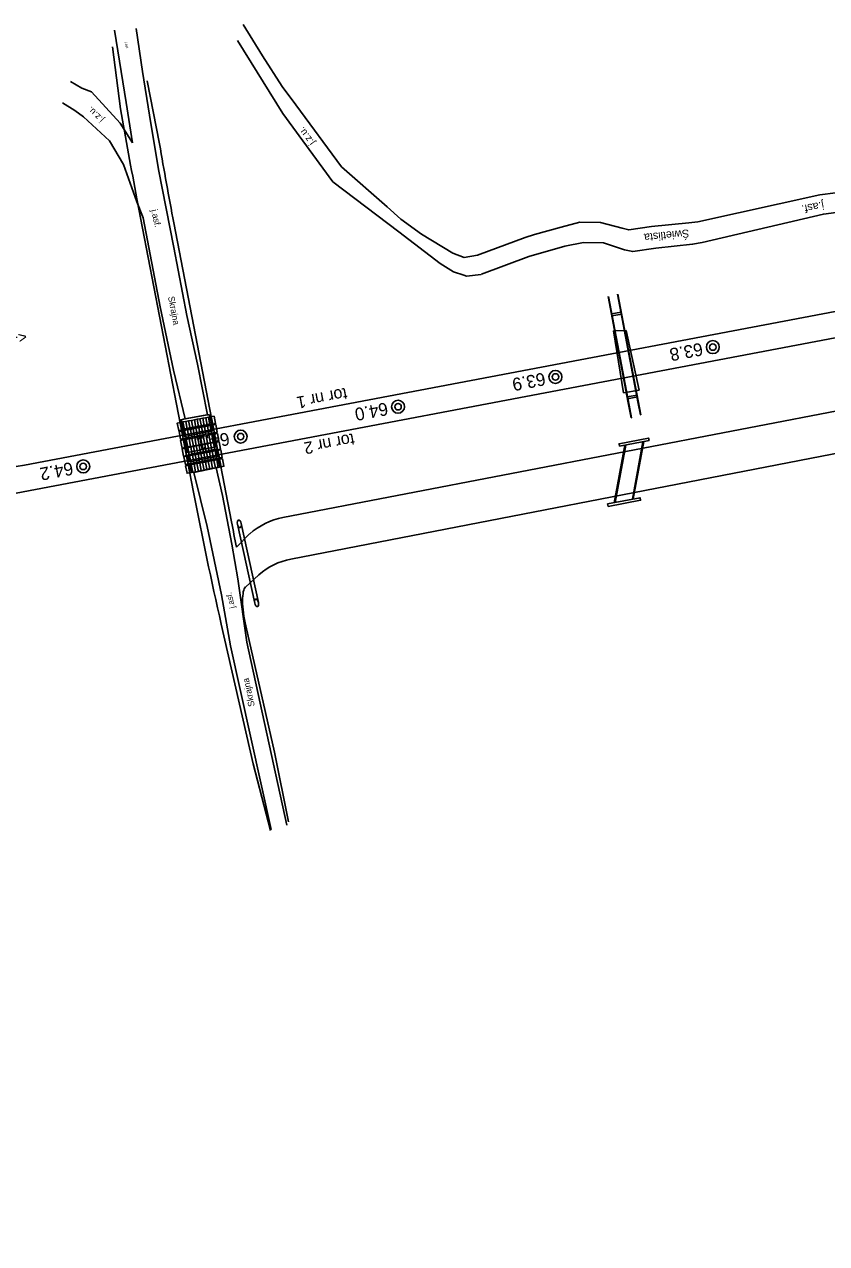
# Model space of a CAD drawing. Extents: x 6541740 to 6556805, y 5525233 to 5530361.
# Drawn here: x 6556529 to 6556654.1, y 5525917.2 to 5526107.6 of the extents above; entities that cross this region are included whole.
import ezdxf

# ---------------------------------------------------------------- set-up
doc = ezdxf.new("R2010")
doc.units = 0
for name, color, linetype in [('Default', 7, 'Continuous'), ('TOR_PS_OPIS_T-numeracja torow i rozjazdow', 7, 'Continuous'), ('TOR_SCH-hektometry', 7, 'Continuous'), ('TOR_SCH-obiekty istniejace', 7, 'Continuous'), ('TOR_SCH-obiekty projektowane', 7, 'Continuous'), ('TOR_SCH-opisy dodatkowe', 7, 'Continuous'), ('TOR_SCH-przejazdy+drogi istniejace', 7, 'Continuous'), ('TOR_SCH-przejazdy+drogi projektowane', 7, 'Continuous'), ('TOR_SCH-tory projektowane', 7, 'Continuous')]:
    doc.layers.add(name, color=color, linetype=linetype)

# ---------------------------------------------------------------- blocks, each defined once
blk = doc.blocks.new('4010_1')
at = {"layer": 'Default'}
for radius in [0.75, 0.375]:
    blk.add_circle((0, 0), radius, dxfattribs=at)

msp = doc.modelspace()

# ---------------------------------------------------------------- linework, layer by layer
at = {"layer": 'Default'}
for points in [[(6556556.79, 5526046.09), (6556557.02, 5526044.91), (6556556.58, 5526044.83), (6556556.35, 5526046.01)], [(6556557.5, 5526044.85), (6556557.72, 5526043.67), (6556557.28, 5526043.59), (6556557.06, 5526044.77)], [(6556557.94, 5526044.94), (6556558.17, 5526043.76), (6556557.72, 5526043.67), (6556557.5, 5526044.85)], [(6556556.23, 5526041.84), (6556556.45, 5526040.67), (6556556.01, 5526040.58), (6556555.78, 5526041.76)]]:
    msp.add_lwpolyline(points, close=True, dxfattribs=at)
at = {"layer": 'TOR_SCH-obiekty istniejace'}
for p, q in [((6556620.88, 5526059.73), (6556622.87, 5526059.79)), ((6556622.44, 5526050.06), (6556620.88, 5526059.73)), ((6556622.87, 5526059.79), (6556624.87, 5526050.5)), ((6556624.87, 5526050.5), (6556622.44, 5526050.06))]:
    msp.add_line(p, q, dxfattribs=at)
at = {"layer": 'TOR_SCH-obiekty projektowane'}
for p, q in [((6556620.04, 5526065.09), (6556623.18, 5526048.52)), ((6556620.11, 5526065.11), (6556623.33, 5526048.14)), ((6556621.5, 5526065.45), (6556624.73, 5526048.4)), ((6556621.57, 5526065.46), (6556624.73, 5526048.81)), ((6556623.18, 5526048.52), (6556623.63, 5526046.17)), ((6556623.33, 5526048.14), (6556623.7, 5526046.18)), ((6556624.73, 5526048.81), (6556625.15, 5526046.61)), ((6556624.73, 5526048.4), (6556625.07, 5526046.6)), ((6556622.65, 5526041.89), (6556621, 5526032.91)), ((6556622.78, 5526041.91), (6556621.14, 5526032.94)), ((6556625.48, 5526042.43), (6556623.84, 5526033.46)), ((6556625.62, 5526042.46), (6556623.97, 5526033.49)), ((6556562.2, 5526029.53), (6556564.89, 5526017.21)), ((6556562.78, 5526029.67), (6556565.47, 5526017.35))]:
    msp.add_line(p, q, dxfattribs=at)
for points in [[(6556620.56, 5526062.37), (6556622.1, 5526062.66)], [(6556620.61, 5526062.07), (6556622.16, 5526062.36)], [(6556623.01, 5526049.41), (6556624.56, 5526049.71)], [(6556623.07, 5526049.12), (6556624.61, 5526049.41)], [(6556623.63, 5526046.17), (6556623.7, 5526046.18)], [(6556625.07, 5526046.6), (6556625.15, 5526046.61)]]:
    msp.add_lwpolyline(points, dxfattribs=at)
for points in [[(6556621.83, 5526041.73), (6556621.76, 5526042.12), (6556626.36, 5526043), (6556626.43, 5526042.61)], [(6556620.03, 5526032.31), (6556619.95, 5526032.71), (6556625.02, 5526033.68), (6556625.1, 5526033.29)]]:
    msp.add_lwpolyline(points, close=True, dxfattribs=at)
for centre in [(6556562.49, 5526029.6), (6556565.18, 5526017.28)]:
    msp.add_ellipse(centre, major_axis=(-0.124, 0.587), ratio=0.500167, dxfattribs=at)
at = {"layer": 'TOR_SCH-przejazdy+drogi istniejace'}
for p, q in [((6556566.12, 5526102.68), (6556563.09, 5526107.58)), ((6556562.19, 5526105.07), (6556569.27, 5526093.69)), ((6556569.19, 5526097.91), (6556566.12, 5526102.68)), ((6556543.91, 5526092.16), (6556539.4, 5526097.06)), ((6556571.32, 5526095), (6556569.19, 5526097.91)), ((6556545.84, 5526089.07), (6556544.84, 5526095.37)), ((6556578.46, 5526085.36), (6556571.32, 5526095)), ((6556538.15, 5526093.17), (6556542.21, 5526089.4)), ((6556548.46, 5526093.42), (6556549.89, 5526084.94)), ((6556569.27, 5526093.69), (6556577.09, 5526082.98)), ((6556545.84, 5526089.07), (6556543.91, 5526092.16)), ((6556542.21, 5526089.4), (6556544.42, 5526085.72)), ((6556544.42, 5526085.72), (6556546.5, 5526079.87)), ((6556585.58, 5526079.09), (6556578.46, 5526085.36)), ((6556577.09, 5526082.98), (6556587.37, 5526075.17)), ((6556587.69, 5526077.17), (6556585.58, 5526079.09)), ((6556590.92, 5526074.81), (6556587.69, 5526077.17)), ((6556587.37, 5526075.17), (6556593.84, 5526070.23)), ((6556595.79, 5526071.85), (6556590.92, 5526074.81)), ((6556593.84, 5526070.23), (6556595.9, 5526068.96)), ((6556556.62, 5526037.87), (6556557.78, 5526038.17)), ((6556567.45, 5525981.86), (6556561.11, 5526010.54)), ((6556563.65, 5526011.12), (6556569.88, 5525982.58))]:
    msp.add_line(p, q, dxfattribs=at)
for points in [[(6556544.84, 5526095.37), (6556543.03, 5526106.68)], [(6556546.4, 5526106.96), (6556547.4, 5526100.21), (6556548.46, 5526093.42)], [(6556539.4, 5526097.06), (6556537.92, 5526097.65), (6556536.16, 5526098.68)], [(6556538.15, 5526093.17), (6556536.82, 5526094.13), (6556534.92, 5526095.32)], [(6556547.48, 5526077.39), (6556550.14, 5526063.49), (6556552.22, 5526053.59), (6556554.05, 5526045.99), (6556557.51, 5526046.62), (6556555.96, 5526054.51), (6556554.32, 5526062.14), (6556552.27, 5526072.74), (6556549.89, 5526084.94)], [(6556634.04, 5526076.74), (6556653.08, 5526080.96), (6556662.87, 5526082.23), (6556670.25, 5526085.15), (6556671.73, 5526085.15), (6556673.8, 5526083.86)], [(6556634.74, 5526073.51), (6556653.64, 5526077.98), (6556663.43, 5526079.25), (6556670.97, 5526081.74), (6556670.97, 5526081.74), (6556673.35, 5526080.43)], [(6556546.5, 5526079.87), (6556547.48, 5526077.39)], [(6556599.66, 5526071.57), (6556607.07, 5526074.33), (6556608.55, 5526074.76), (6556612.72, 5526075.95), (6556615.61, 5526076.71), (6556618.84, 5526076.67), (6556622.22, 5526075.78), (6556623.25, 5526075.5), (6556626.83, 5526076.01), (6556632.64, 5526076.59), (6556634.04, 5526076.74)], [(6556600.26, 5526068.57), (6556607.67, 5526071.33), (6556613.31, 5526072.95), (6556616.18, 5526073.53), (6556619.34, 5526073.49), (6556622.58, 5526072.37), (6556623.88, 5526072.12), (6556627.46, 5526072.63), (6556633.22, 5526073.25), (6556634.74, 5526073.51)], [(6556595.79, 5526071.85), (6556597.57, 5526071.19), (6556599.66, 5526071.57)], [(6556595.9, 5526068.96), (6556597.55, 5526068.42), (6556597.94, 5526068.3), (6556600.24, 5526068.56)], [(6556563.65, 5526011.12), (6556562.26, 5526021.02), (6556561.34, 5526026.41), (6556559.86, 5526034.01), (6556558.88, 5526038.37), (6556555.37, 5526037.64), (6556557.46, 5526029.19), (6556559.71, 5526018.51), (6556561.11, 5526010.54)]]:
    msp.add_lwpolyline(points, dxfattribs=at)
for points in [[(6556557.84, 5526046.63), (6556558.13, 5526045.2), (6556553.7, 5526044.39), (6556553.4, 5526045.87), (6556553.99, 5526045.98), (6556557.44, 5526046.61)], [(6556553.7, 5526044.39), (6556558.14, 5526045.2), (6556558.35, 5526044.13), (6556553.92, 5526043.26)], [(6556553.96, 5526042.94), (6556558.38, 5526043.83), (6556558.83, 5526041.61), (6556554.39, 5526040.75)], [(6556554.44, 5526040.39), (6556558.87, 5526041.27), (6556559.11, 5526040.11), (6556554.66, 5526039.27)], [(6556554.75, 5526038.89), (6556559.19, 5526039.74), (6556559.44, 5526038.49), (6556558.95, 5526038.39), (6556555.44, 5526037.65), (6556555.01, 5526037.61)]]:
    msp.add_lwpolyline(points, close=True, dxfattribs=at)
at = {"layer": 'TOR_SCH-przejazdy+drogi projektowane'}
for p, q in [((6556543.97, 5526094.39), (6556542.71, 5526104.08)), ((6556548.11, 5526098.78), (6556550.05, 5526088.91)), ((6556555.34, 5526034.54), (6556546.52, 5526080.37)), ((6556552.28, 5526076.59), (6556561.27, 5526029.93)), ((6556679.79, 5526051.86), (6556569.29, 5526030.59)), ((6556570.53, 5526024.1), (6556677.39, 5526044.81)), ((6556564.1, 5526028.03), (6556562.05, 5526025.96)), ((6556563.45, 5526019.74), (6556565.55, 5526021.66))]:
    msp.add_line(p, q, dxfattribs=at)
for points in [[(6556553.7, 5526045.51), (6556553.92, 5526044.33), (6556553.48, 5526044.25), (6556553.26, 5526045.42)], [(6556554.14, 5526045.59), (6556554.37, 5526044.41), (6556553.92, 5526044.33), (6556553.7, 5526045.51)], [(6556554.58, 5526045.68), (6556554.81, 5526044.5), (6556554.37, 5526044.41), (6556554.14, 5526045.59)], [(6556555.03, 5526045.76), (6556555.25, 5526044.58), (6556554.81, 5526044.5), (6556554.58, 5526045.68)], [(6556555.47, 5526045.84), (6556555.69, 5526044.66), (6556555.25, 5526044.58), (6556555.03, 5526045.76)], [(6556555.91, 5526045.93), (6556556.14, 5526044.75), (6556555.69, 5526044.66), (6556555.47, 5526045.84)], [(6556556.35, 5526046.01), (6556556.58, 5526044.83), (6556556.14, 5526044.75), (6556555.91, 5526045.93)], [(6556557.24, 5526046.18), (6556557.46, 5526045), (6556557.02, 5526044.91), (6556556.79, 5526046.09)], [(6556557.68, 5526046.26), (6556557.9, 5526045.08), (6556557.46, 5526045), (6556557.24, 5526046.18)], [(6556558.12, 5526046.34), (6556558.35, 5526045.17), (6556557.9, 5526045.08), (6556557.68, 5526046.26)], [(6556558.56, 5526046.43), (6556558.79, 5526045.25), (6556558.35, 5526045.17), (6556558.12, 5526046.34)], [(6556553.26, 5526045.42), (6556553.48, 5526044.25), (6556553.04, 5526044.16), (6556552.81, 5526045.34)], [(6556553.52, 5526044.1), (6556553.74, 5526042.92), (6556553.3, 5526042.84), (6556553.08, 5526044.02)], [(6556553.96, 5526044.18), (6556554.19, 5526043.01), (6556553.74, 5526042.92), (6556553.52, 5526044.1)], [(6556554.4, 5526044.27), (6556554.63, 5526043.09), (6556554.19, 5526043.01), (6556553.96, 5526044.18)], [(6556554.85, 5526044.35), (6556555.07, 5526043.17), (6556554.63, 5526043.09), (6556554.4, 5526044.27)], [(6556555.29, 5526044.44), (6556555.51, 5526043.26), (6556555.07, 5526043.17), (6556554.85, 5526044.35)], [(6556555.73, 5526044.52), (6556555.96, 5526043.34), (6556555.51, 5526043.26), (6556555.29, 5526044.44)], [(6556556.17, 5526044.6), (6556556.4, 5526043.42), (6556555.96, 5526043.34), (6556555.73, 5526044.52)], [(6556556.61, 5526044.69), (6556556.84, 5526043.51), (6556556.4, 5526043.42), (6556556.17, 5526044.6)], [(6556557.06, 5526044.77), (6556557.28, 5526043.59), (6556556.84, 5526043.51), (6556556.61, 5526044.69)], [(6556558.38, 5526045.02), (6556558.61, 5526043.84), (6556558.17, 5526043.76), (6556557.94, 5526044.94)], [(6556558.64, 5526043.62), (6556558.86, 5526042.44), (6556558.42, 5526042.36), (6556558.2, 5526043.54)], [(6556558.83, 5526045.1), (6556559.05, 5526043.93), (6556558.61, 5526043.84), (6556558.38, 5526045.02)], [(6556559.08, 5526043.7), (6556559.3, 5526042.52), (6556558.86, 5526042.44), (6556558.64, 5526043.62)], [(6556553.77, 5526042.7), (6556554, 5526041.52), (6556553.56, 5526041.44), (6556553.33, 5526042.62)], [(6556554.22, 5526042.78), (6556554.44, 5526041.61), (6556554, 5526041.52), (6556553.77, 5526042.7)], [(6556554.66, 5526042.87), (6556554.88, 5526041.69), (6556554.44, 5526041.61), (6556554.22, 5526042.78)], [(6556555.1, 5526042.95), (6556555.32, 5526041.77), (6556554.88, 5526041.69), (6556554.66, 5526042.87)], [(6556555.54, 5526043.03), (6556555.77, 5526041.86), (6556555.32, 5526041.77), (6556555.1, 5526042.95)], [(6556555.78, 5526041.76), (6556556.01, 5526040.58), (6556555.57, 5526040.5), (6556555.34, 5526041.68)], [(6556555.98, 5526043.12), (6556556.21, 5526041.94), (6556555.77, 5526041.86), (6556555.54, 5526043.03)], [(6556556.43, 5526043.2), (6556556.65, 5526042.02), (6556556.21, 5526041.94), (6556555.98, 5526043.12)], [(6556556.67, 5526041.93), (6556556.89, 5526040.75), (6556556.45, 5526040.67), (6556556.23, 5526041.84)], [(6556556.87, 5526043.29), (6556557.09, 5526042.11), (6556556.65, 5526042.02), (6556556.43, 5526043.2)], [(6556557.11, 5526042.01), (6556557.34, 5526040.83), (6556556.89, 5526040.75), (6556556.67, 5526041.93)], [(6556557.31, 5526043.37), (6556557.54, 5526042.19), (6556557.09, 5526042.11), (6556556.87, 5526043.29)], [(6556557.55, 5526042.09), (6556557.78, 5526040.92), (6556557.34, 5526040.83), (6556557.11, 5526042.01)], [(6556557.75, 5526043.45), (6556557.98, 5526042.27), (6556557.54, 5526042.19), (6556557.31, 5526043.37)], [(6556557.99, 5526042.18), (6556558.22, 5526041), (6556557.78, 5526040.92), (6556557.55, 5526042.09)], [(6556558.2, 5526043.54), (6556558.42, 5526042.36), (6556557.98, 5526042.27), (6556557.75, 5526043.45)], [(6556558.44, 5526042.26), (6556558.66, 5526041.08), (6556558.22, 5526041), (6556557.99, 5526042.18)], [(6556558.88, 5526042.35), (6556559.1, 5526041.17), (6556558.66, 5526041.08), (6556558.44, 5526042.26)], [(6556559.32, 5526042.43), (6556559.55, 5526041.25), (6556559.1, 5526041.17), (6556558.88, 5526042.35)], [(6556554.02, 5526041.43), (6556554.24, 5526040.25), (6556553.8, 5526040.16), (6556553.57, 5526041.34)], [(6556554.29, 5526040.15), (6556554.51, 5526038.97), (6556554.07, 5526038.88), (6556553.84, 5526040.06)], [(6556554.46, 5526041.51), (6556554.68, 5526040.33), (6556554.24, 5526040.25), (6556554.02, 5526041.43)], [(6556554.73, 5526040.23), (6556554.95, 5526039.05), (6556554.51, 5526038.97), (6556554.29, 5526040.15)], [(6556554.9, 5526041.59), (6556555.12, 5526040.41), (6556554.68, 5526040.33), (6556554.46, 5526041.51)], [(6556555.17, 5526040.31), (6556555.4, 5526039.13), (6556554.95, 5526039.05), (6556554.73, 5526040.23)], [(6556555.34, 5526041.68), (6556555.57, 5526040.5), (6556555.12, 5526040.41), (6556554.9, 5526041.59)], [(6556555.61, 5526040.4), (6556555.84, 5526039.22), (6556555.4, 5526039.13), (6556555.17, 5526040.31)], [(6556556.06, 5526040.48), (6556556.28, 5526039.3), (6556555.84, 5526039.22), (6556555.61, 5526040.4)], [(6556556.5, 5526040.56), (6556556.72, 5526039.38), (6556556.28, 5526039.3), (6556556.06, 5526040.48)], [(6556556.94, 5526040.65), (6556557.16, 5526039.47), (6556556.72, 5526039.38), (6556556.5, 5526040.56)], [(6556557.38, 5526040.73), (6556557.61, 5526039.55), (6556557.16, 5526039.47), (6556556.94, 5526040.65)], [(6556557.82, 5526040.81), (6556558.05, 5526039.64), (6556557.61, 5526039.55), (6556557.38, 5526040.73)], [(6556558.27, 5526040.9), (6556558.49, 5526039.72), (6556558.05, 5526039.64), (6556557.82, 5526040.81)], [(6556558.71, 5526040.98), (6556558.93, 5526039.8), (6556558.49, 5526039.72), (6556558.27, 5526040.9)], [(6556559.15, 5526041.07), (6556559.38, 5526039.89), (6556558.93, 5526039.8), (6556558.71, 5526040.98)], [(6556559.59, 5526041.15), (6556559.82, 5526039.97), (6556559.38, 5526039.89), (6556559.15, 5526041.07)], [(6556554.55, 5526038.76), (6556554.77, 5526037.58), (6556554.33, 5526037.5), (6556554.11, 5526038.68)], [(6556554.99, 5526038.85), (6556555.22, 5526037.67), (6556554.77, 5526037.58), (6556554.55, 5526038.76)], [(6556555.43, 5526038.93), (6556555.66, 5526037.75), (6556555.22, 5526037.67), (6556554.99, 5526038.85)], [(6556555.87, 5526039.01), (6556556.1, 5526037.83), (6556555.66, 5526037.75), (6556555.43, 5526038.93)], [(6556556.32, 5526039.1), (6556556.54, 5526037.92), (6556556.1, 5526037.83), (6556555.87, 5526039.01)], [(6556556.76, 5526039.18), (6556556.98, 5526038), (6556556.54, 5526037.92), (6556556.32, 5526039.1)], [(6556557.2, 5526039.26), (6556557.43, 5526038.09), (6556556.98, 5526038), (6556556.76, 5526039.18)], [(6556557.64, 5526039.35), (6556557.87, 5526038.17), (6556557.43, 5526038.09), (6556557.2, 5526039.26)], [(6556558.09, 5526039.43), (6556558.31, 5526038.25), (6556557.87, 5526038.17), (6556557.64, 5526039.35)], [(6556558.53, 5526039.51), (6556558.75, 5526038.34), (6556558.31, 5526038.25), (6556558.09, 5526039.43)], [(6556558.97, 5526039.6), (6556559.19, 5526038.42), (6556558.75, 5526038.34), (6556558.53, 5526039.51)], [(6556559.41, 5526039.68), (6556559.64, 5526038.5), (6556559.19, 5526038.42), (6556558.97, 5526039.6)], [(6556559.85, 5526039.77), (6556560.08, 5526038.59), (6556559.64, 5526038.5), (6556559.41, 5526039.68)]]:
    msp.add_lwpolyline(points, close=True, dxfattribs=at)
for points in [[(6556567.37, 5525981.75), (6556564.66, 5525992.16), (6556559.68, 5526013.95)], [(6556570.17, 5525983.06), (6556568, 5525993.95), (6556563.49, 5526013.67)]]:
    msp.add_lwpolyline(points, dxfattribs=at)
for centre, major_axis, ratio, start_param, end_param in [((6556583.72, 5526090.12), (-28.59, 150.81), 0.25, 1.495124, 1.588056), ((6556587.94, 5526085.1), (-27.28, 143.94), 0.25, 1.496955, 1.58251), ((6556592.71, 5526043.46), (-28.59, 150.81), 0.25, 1.58251, 1.720156), ((6556571.4, 5526019.66), (-2.1, 10.93), 0.98976, 0, 0.531351), ((6556596.93, 5526038.43), (-27.28, 143.94), 0.25, 1.58251, 1.610126), ((6556572.52, 5526013.74), (-7.92, -6.97), 0.999824, 4.181038, 4.712389), ((6556564.62, 5526014.68), (-0.98, 5.16), 0.25, 0.146839, 1.720156), ((6556563.45, 5526019.74), (-0.0000000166, -0.0000000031), 0.990774, 4.859228, 4.957279)]:
    msp.add_ellipse(centre, major_axis=major_axis, ratio=ratio, start_param=start_param, end_param=end_param, dxfattribs=at)
at = {"layer": 'TOR_SCH-tory projektowane'}
for p, q in [((6556734.28, 5526077.71), (6556528.95, 5526038.79)), ((6556735.03, 5526073.73), (6555909.41, 5525917.23))]:
    msp.add_line(p, q, dxfattribs=at)
msp.add_ellipse((6550392.46, 5558412.33), major_axis=(-6136.5, 32373.54), ratio=0.25, start_param=3.139013, end_param=3.141593, dxfattribs=at)

# ---------------------------------------------------------------- block references
at = {"layer": 'Default', "xscale": 1.345963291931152, "yscale": 1.345963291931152}
msp.add_blockref('4010_1', (6556562.7, 5526043.23), dxfattribs=at)
at = {"layer": 'TOR_SCH-hektometry', "xscale": 1.345963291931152, "yscale": 1.345963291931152}
for p in [(6556636.38, 5526057.2), (6556611.82, 5526052.54), (6556587.26, 5526047.89), (6556562.7, 5526043.23), (6556538.13, 5526038.57)]:
    msp.add_blockref('4010_1', p, dxfattribs=at)

# ---------------------------------------------------------------- texts
at = {"layer": 'Default'}
msp.add_text('64.1', height=2, rotation=190.7691, dxfattribs=at).set_placement((6556560.76, 5526043.91))
at = {"layer": 'TOR_PS_OPIS_T-numeracja torow i rozjazdow'}
for s, p in [('tor nr 1', (6556579.12, 5526050.87)), ('tor nr 2', (6556580.26, 5526043.76))]:
    msp.add_text(s, height=1.875, rotation=190.7101, dxfattribs=at).set_placement(p)
at = {"layer": 'TOR_SCH-hektometry'}
for s, p in [('63.8', (6556634.61, 5526057.91)), ('63.9', (6556610.05, 5526053.25)), ('64.0', (6556585.48, 5526048.59)), ('64.2', (6556536.35, 5526039.28))]:
    msp.add_text(s, height=2, rotation=190.7691, dxfattribs=at).set_placement(p)
at = {"layer": 'TOR_SCH-opisy dodatkowe'}
msp.add_text('<--- kierunek: Chybie', height=1.75, rotation=191.0012, dxfattribs=at).set_placement((6556529.17, 5526059.69))
at = {"layer": 'TOR_SCH-przejazdy+drogi istniejace'}
for s, height, rotation, p in [('j.asf.', 0.37, 278.3537, (6556544.66, 5526104.8)), ('j.z.u.', 1.022, 135.7801, (6556541.44, 5526092.83)), ('j.z.u.', 1.115, 126.1179, (6556574.32, 5526089.17)), ('j.asf.', 1.244, 190.9329, (6556653.6, 5526079.96)), ('j.asf.', 1, 282.7811, (6556548.72, 5526078.58)), ('Świetlista', 1.25, 185.8212, (6556632.62, 5526075.59)), ('Skrajna', 1, 280.953, (6556551.36, 5526065.04)), ('j.asf.', 0.9, 103.1537, (6556561.83, 5526016.51)), ('Skrajna', 1, 102.3379, (6556564.91, 5526001.19))]:
    msp.add_text(s, height=height, rotation=rotation, dxfattribs=at).set_placement(p)

doc.saveas('drawing.dxf')
